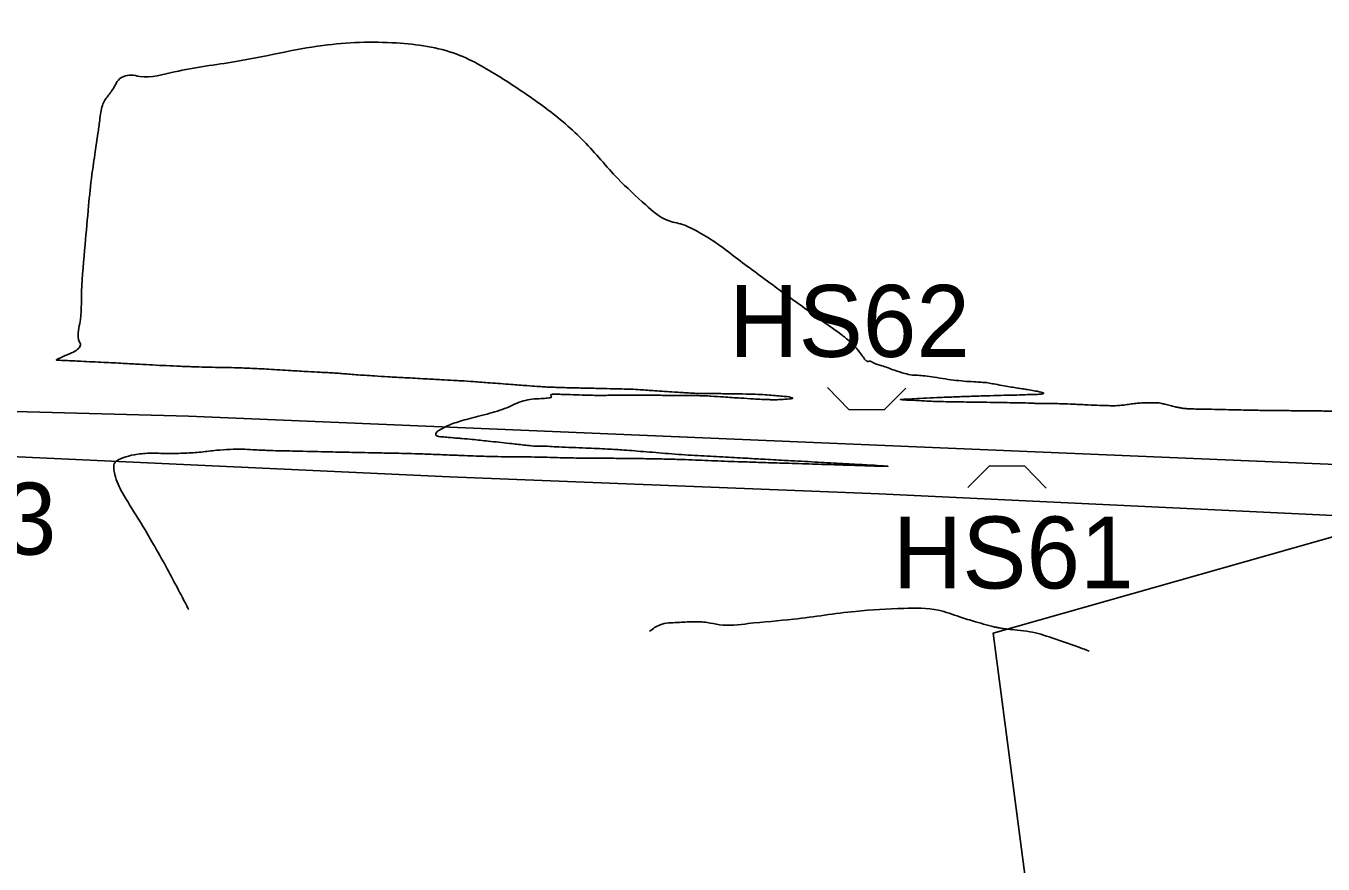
# Model space of a CAD drawing. Extents: x -478232 to -472707, y -1118753 to -1113967.
# Drawn here: x -477613.4 to -477433.2, y -1117465.6 to -1117349.2 of the extents above; entities that cross this region are included whole.
import ezdxf

# ---------------------------------------------------------------- set-up
doc = ezdxf.new("R2010")
doc.units = 0
for name, color, linetype in [('DESQ_pomoc', 7, 'Continuous'), ('hospodářské sjezdy', 7, 'Continuous'), ('ObPÚ', 7, 'Continuous'), ('silnice', 7, 'Continuous'), ('Vrstevnice_vedlejsi', 7, 'Continuous')]:
    doc.layers.add(name, color=color, linetype=linetype)

msp = doc.modelspace()

# ---------------------------------------------------------------- linework, layer by layer
at = {"layer": 'DESQ_pomoc'}
msp.add_lwpolyline([(-477421.557, -1117417.2), (-477479.012, -1117433.518), (-477472.878, -1117480.495), (-477481.667, -1117549.548), (-477467.907, -1117654.92), (-477462.841, -1117804.599), (-477459.217, -1117906.221), (-477463.956, -1117960.587), (-477418.233, -1118072.943), (-477384.22, -1118141.946), (-477344.067, -1118184.315), (-477265.129, -1118290.773), (-477142.501, -1118220.428)], dxfattribs=at)
at = {"layer": 'hospodářské sjezdy'}
for p, q in [((-477499.054, -1117402.428), (-477502.044, -1117399.386)), ((-477491.124, -1117399.487), (-477494.169, -1117402.473)), ((-477494.169, -1117402.473), (-477499.054, -1117402.428)), ((-477482.552, -1117413.268), (-477479.505, -1117410.283)), ((-477479.505, -1117410.283), (-477474.62, -1117410.33)), ((-477474.62, -1117410.33), (-477471.631, -1117413.373))]:
    msp.add_line(p, q, dxfattribs=at)
at = {"layer": 'ObPÚ'}
msp.add_lwpolyline([(-477428.82, -1117417.33), (-477494.83, -1117414.18), (-477554.51, -1117411.78), (-477621.5, -1117408.68), (-477644.72, -1117408.28), (-477682.13, -1117413.46), (-477685.93, -1117414.02), (-477688.8, -1117414.36), (-477691.73, -1117414.77), (-477738.55, -1117419.44), (-477782.49, -1117430.5), (-477808.98, -1117437.26), (-477845.5, -1117449.81), (-477945.12, -1117479.46), (-478009.37, -1117499.81)], dxfattribs=at)
at = {"layer": 'silnice'}
msp.add_lwpolyline([(-478068.596, -1117511.329), (-477917.95, -1117462.993), (-477779.219, -1117418.245), (-477732.944, -1117407.585), (-477720.808, -1117405.048), (-477704.588, -1117403.835), (-477689.402, -1117401.926), (-477652.852, -1117401.691), (-477590.784, -1117403.37), (-477332.447, -1117414.279), (-477204.956, -1117416.797), (-477142.049, -1117416.797), (-477096.756, -1117410.083), (-477036.34, -1117397.174), (-476978.492, -1117379.033), (-476883.712, -1117344.626), (-476756.221, -1117298.47), (-476633.763, -1117254.832), (-476588.47, -1117242.245), (-476550.726, -1117234.692), (-476503.755, -1117230.496), (-476424.073, -1117228.817), (-476282.324, -1117220.425)], dxfattribs=at)
at = {"layer": 'Vrstevnice_vedlejsi'}
for points in [[(-477242.816, -1117401.206), (-477242.33, -1117400.788), (-477241.801, -1117400.341), (-477241.229, -1117399.866), (-477240.615, -1117399.363), (-477236.987, -1117397.929), (-477230.346, -1117395.561), (-477220.692, -1117392.262), (-477213.029, -1117389.419), (-477207.358, -1117387.033), (-477203.679, -1117385.104), (-477198.765, -1117383.705), (-477192.616, -1117382.835), (-477185.231, -1117382.494), (-477180.359, -1117379.804), (-477178.001, -1117374.763), (-477178.155, -1117367.373), (-477179.951, -1117358.721), (-477183.387, -1117348.807), (-477188.465, -1117337.631), (-477192.245, -1117329.464), (-477194.727, -1117324.304), (-477195.91, -1117322.151), (-477197.022, -1117320.01), (-477198.062, -1117317.881), (-477199.031, -1117315.762), (-477201.828, -1117310.612), (-477206.453, -1117302.429), (-477212.906, -1117291.215), (-477218.991, -1117279.805), (-477224.706, -1117268.2), (-477230.053, -1117256.4), (-477233.791, -1117248.023), (-477235.922, -1117243.067), (-477236.445, -1117241.534), (-477237.131, -1117240.196), (-477237.979, -1117239.054), (-477238.989, -1117238.108), (-477240.099, -1117237.792), (-477241.308, -1117238.108), (-477242.616, -1117239.054), (-477247.496, -1117242.927), (-477255.949, -1117249.728), (-477267.975, -1117259.456), (-477276.908, -1117266.227), (-477282.75, -1117270.039), (-477285.501, -1117270.894), (-477290.862, -1117272.253), (-477298.834, -1117274.115), (-477309.417, -1117276.481), (-477320.28, -1117277.55), (-477331.422, -1117277.32), (-477342.843, -1117275.793), (-477351.095, -1117274.483), (-477356.177, -1117273.39), (-477358.088, -1117272.515), (-477363.807, -1117268.569), (-477373.333, -1117261.552), (-477386.667, -1117251.464), (-477395.708, -1117244.586), (-477400.459, -1117240.917), (-477400.917, -1117240.459), (-477405.515, -1117237.519), (-477414.252, -1117232.098), (-477427.127, -1117224.195), (-477436.796, -1117218.202), (-477443.259, -1117214.119), (-477446.516, -1117211.946), (-477449.727, -1117209.411), (-477452.893, -1117206.515), (-477456.014, -1117203.258), (-477459.048, -1117199.241), (-477461.994, -1117194.464), (-477464.853, -1117188.928), (-477466.734, -1117184.683), (-477467.638, -1117181.729), (-477467.564, -1117180.066), (-477467.628, -1117178.904), (-477467.829, -1117178.243), (-477468.169, -1117178.084), (-477468.447, -1117177.976), (-477468.662, -1117177.92), (-477468.815, -1117177.914), (-477468.774, -1117177.844), (-477468.538, -1117177.708), (-477468.108, -1117177.506), (-477467.675, -1117177.3), (-477467.24, -1117177.089), (-477466.803, -1117176.874), (-477466.105, -1117176.551), (-477465.147, -1117176.119), (-477463.929, -1117175.579), (-477461.972, -1117174.773), (-477459.277, -1117173.703), (-477455.843, -1117172.368), (-477453.286, -1117171.289), (-477451.604, -1117170.465)], [(-477560, -1117291.244), (-477566.955, -1117290.703), (-477572.559, -1117290.73), (-477580.289, -1117291.053), (-477590.144, -1117291.672), (-477599.448, -1117292.43), (-477608.201, -1117293.327), (-477616.402, -1117294.362), (-477623.179, -1117297.786), (-477628.532, -1117303.598), (-477632.462, -1117311.799), (-477635.234, -1117317.515), (-477636.85, -1117320.745), (-477637.308, -1117321.489), (-477637.862, -1117322.307), (-477638.511, -1117323.197), (-477639.255, -1117324.161), (-477640.286, -1117325.39), (-477641.603, -1117326.884), (-477643.205, -1117328.643), (-477644.962, -1117330.8), (-477646.874, -1117333.353), (-477648.94, -1117336.304), (-477650.379, -1117338.35), (-477651.193, -1117339.491), (-477651.38, -1117339.728), (-477651.613, -1117339.807), (-477651.892, -1117339.73), (-477652.217, -1117339.495), (-477652.693, -1117339.69), (-477653.319, -1117340.312), (-477654.095, -1117341.364), (-477655.093, -1117343.008), (-477656.315, -1117345.246), (-477657.76, -1117348.077), (-477658.682, -1117350.137), (-477659.083, -1117351.426), (-477658.962, -1117351.944), (-477659.599, -1117353.56), (-477660.994, -1117356.275), (-477663.148, -1117360.088), (-477664.694, -1117362.921), (-477665.633, -1117364.773), (-477665.966, -1117365.645), (-477666.773, -1117366.866), (-477668.055, -1117368.437), (-477669.813, -1117370.359), (-477671.229, -1117372.05), (-477672.304, -1117373.51), (-477673.037, -1117374.74), (-477673.862, -1117375.748), (-477674.779, -1117376.534), (-477675.788, -1117377.099), (-477676.742, -1117377.638), (-477677.641, -1117378.153), (-477678.485, -1117378.642), (-477679.333, -1117379.521), (-477680.185, -1117380.789), (-477681.041, -1117382.447), (-477681.49, -1117384.046), (-477681.533, -1117385.585), (-477681.168, -1117387.067), (-477681.316, -1117388.188), (-477681.976, -1117388.95), (-477683.149, -1117389.352), (-477683.785, -1117390.175), (-477683.885, -1117391.417), (-477683.449, -1117393.079), (-477683.513, -1117394.312), (-477684.078, -1117395.114), (-477685.144, -1117395.487), (-477685.939, -1117395.751), (-477686.463, -1117395.907), (-477686.718, -1117395.954), (-477686.939, -1117395.99), (-477687.126, -1117396.014), (-477687.279, -1117396.025), (-477687.704, -1117396.038), (-477688.399, -1117396.053), (-477689.366, -1117396.069), (-477690.19, -1117395.962), (-477690.871, -1117395.732), (-477691.409, -1117395.38), (-477691.907, -1117395.109), (-477692.367, -1117394.92), (-477692.788, -1117394.813), (-477693.123, -1117394.709), (-477693.373, -1117394.61), (-477693.537, -1117394.515), (-477693.67, -1117394.45), (-477693.774, -1117394.413), (-477693.847, -1117394.406), (-477693.928, -1117394.43), (-477694.017, -1117394.485), (-477694.114, -1117394.571), (-477694.592, -1117394.718), (-477695.45, -1117394.927)], [(-477495.127, -1117335.127), (-477511.712, -1117338.553), (-477521.011, -1117337.443), (-477531.316, -1117333.51), (-477542.627, -1117326.753), (-477550.841, -1117321.897), (-477555.959, -1117318.94), (-477557.979, -1117317.884), (-477563.123, -1117316.885), (-477571.391, -1117315.942), (-477582.781, -1117315.057), (-477591.023, -1117314.508), (-477596.115, -1117314.294), (-477598.057, -1117314.416), (-477599.891, -1117314.566), (-477601.616, -1117314.742), (-477603.233, -1117314.947), (-477604.569, -1117315.621), (-477605.624, -1117316.767), (-477606.399, -1117318.384), (-477608.304, -1117321.719), (-477611.342, -1117326.774), (-477615.51, -1117333.547), (-477619.979, -1117340.25), (-477624.748, -1117346.881), (-477629.817, -1117353.44), (-477633.361, -1117359.059), (-477635.379, -1117363.738), (-477635.872, -1117367.476), (-477636.56, -1117371.199), (-477637.443, -1117374.909), (-477638.521, -1117378.604), (-477639.377, -1117382.031), (-477640.009, -1117385.19), (-477640.419, -1117388.082), (-477640.785, -1117390.136), (-477641.106, -1117391.354), (-477641.382, -1117391.735), (-477641.698, -1117392.233), (-477642.053, -1117392.847), (-477642.449, -1117393.578), (-477642.545, -1117394.166), (-477642.342, -1117394.61), (-477641.839, -1117394.91), (-477641.625, -1117395.129), (-477641.7, -1117395.269), (-477642.063, -1117395.328), (-477642.557, -1117395.371), (-477643.181, -1117395.398), (-477643.936, -1117395.409), (-477644.487, -1117395.416), (-477644.834, -1117395.419), (-477644.977, -1117395.418), (-477645.44, -1117395.437), (-477646.223, -1117395.478), (-477647.327, -1117395.539), (-477648.287, -1117395.586), (-477649.105, -1117395.618), (-477649.781, -1117395.636), (-477650.529, -1117395.622), (-477651.351, -1117395.575), (-477652.246, -1117395.495), (-477653.089, -1117395.458), (-477653.88, -1117395.466), (-477654.618, -1117395.517), (-477655.514, -1117395.581), (-477656.567, -1117395.657), (-477657.777, -1117395.746), (-477658.796, -1117395.828), (-477659.624, -1117395.904), (-477660.261, -1117395.973), (-477661.317, -1117396.007), (-477662.793, -1117396.004), (-477664.688, -1117395.966), (-477665.997, -1117395.925), (-477666.721, -1117395.883), (-477666.859, -1117395.838), (-477667.114, -1117395.731), (-477667.487, -1117395.563), (-477667.978, -1117395.332), (-477668.383, -1117395.039), (-477668.702, -1117394.683), (-477668.934, -1117394.264), (-477669.163, -1117393.971), (-477669.387, -1117393.804), (-477669.607, -1117393.763), (-477669.885, -1117393.684), (-477670.219, -1117393.568), (-477670.611, -1117393.414), (-477670.803, -1117393.149), (-477670.795, -1117392.772), (-477670.589, -1117392.285), (-477670.483, -1117391.911), (-477670.48, -1117391.65), (-477670.578, -1117391.502), (-477670.739, -1117391.523), (-477670.964, -1117391.713)], [(-477547.057, -1117356.544), (-477553.529, -1117353.088), (-477561.882, -1117351.53), (-477572.116, -1117351.871), (-477584.232, -1117354.11), (-477592.716, -1117355.544), (-477597.566, -1117356.173), (-477598.783, -1117355.997), (-477599.771, -1117356.168), (-477600.531, -1117356.684), (-477601.061, -1117357.546), (-477601.551, -1117358.298), (-477602.002, -1117358.939), (-477602.412, -1117359.469), (-477602.735, -1117360.205), (-477602.973, -1117361.146), (-477603.124, -1117362.291), (-477603.379, -1117364.123), (-477603.738, -1117366.64), (-477604.201, -1117369.843), (-477604.671, -1117374.143), (-477605.147, -1117379.539), (-477605.629, -1117386.031), (-477605.897, -1117390.519), (-477605.953, -1117393.003), (-477605.795, -1117393.483), (-477606.068, -1117393.971), (-477606.774, -1117394.465), (-477607.91, -1117394.966), (-477608.683, -1117395.313), (-477609.09, -1117395.506), (-477609.132, -1117395.543), (-477609.139, -1117395.569), (-477609.111, -1117395.582), (-477609.047, -1117395.583), (-477608.993, -1117395.585), (-477608.95, -1117395.587), (-477608.917, -1117395.589), (-477607.842, -1117395.642), (-477605.725, -1117395.746), (-477602.565, -1117395.902), (-477599.853, -1117396.04), (-477597.587, -1117396.161), (-477595.769, -1117396.264), (-477593.874, -1117396.358), (-477591.902, -1117396.442), (-477589.854, -1117396.517), (-477587.923, -1117396.575), (-477586.108, -1117396.616), (-477584.411, -1117396.64), (-477582.257, -1117396.72), (-477579.647, -1117396.854), (-477576.581, -1117397.043), (-477574.191, -1117397.186), (-477572.476, -1117397.281), (-477571.436, -1117397.33), (-477570.44, -1117397.388), (-477569.488, -1117397.455), (-477568.579, -1117397.532), (-477567.518, -1117397.613), (-477566.304, -1117397.699), (-477564.938, -1117397.79), (-477563.079, -1117397.901), (-477560.727, -1117398.033), (-477557.883, -1117398.185), (-477555.632, -1117398.307), (-477553.973, -1117398.399), (-477552.907, -1117398.461), (-477551.216, -1117398.577), (-477548.9, -1117398.747), (-477545.961, -1117398.971), (-477543.777, -1117399.136), (-477542.351, -1117399.241), (-477541.681, -1117399.287), (-477540.95, -1117399.327), (-477540.156, -1117399.361), (-477539.3, -1117399.389), (-477537.852, -1117399.427), (-477535.812, -1117399.475), (-477533.18, -1117399.533), (-477531.228, -1117399.578), (-477529.955, -1117399.611), (-477529.361, -1117399.631), (-477528.052, -1117399.706), (-477526.027, -1117399.837), (-477523.287, -1117400.022), (-477521.342, -1117400.147), (-477520.193, -1117400.212), (-477519.839, -1117400.216), (-477518.821, -1117400.228), (-477517.138, -1117400.246), (-477514.791, -1117400.271), (-477512.839, -1117400.311), (-477511.284, -1117400.368), (-477510.126, -1117400.44), (-477509.042, -1117400.531), (-477508.034, -1117400.639)], [(-477465.81, -1117401.807), (-477467.853, -1117401.711), (-477469.483, -1117401.65), (-477470.699, -1117401.625), (-477471.502, -1117401.636), (-477472.266, -1117401.631), (-477472.992, -1117401.61), (-477473.68, -1117401.572), (-477475.37, -1117401.529), (-477478.062, -1117401.478), (-477481.757, -1117401.421), (-477484.381, -1117401.381), (-477485.933, -1117401.359), (-477486.415, -1117401.354), (-477487.287, -1117401.321), (-477488.55, -1117401.26), (-477490.204, -1117401.17), (-477491.309, -1117401.11), (-477491.868, -1117401.081), (-477491.878, -1117401.081), (-477491.885, -1117401.08), (-477491.891, -1117401.076), (-477491.893, -1117401.071), (-477491.894, -1117401.067), (-477491.892, -1117401.063), (-477491.887, -1117401.06), (-477491.875, -1117401.058), (-477491.855, -1117401.056), (-477491.827, -1117401.055), (-477491.219, -1117401.024), (-477490.031, -1117400.961), (-477488.263, -1117400.869), (-477486.338, -1117400.78), (-477484.255, -1117400.695), (-477482.016, -1117400.615), (-477479.912, -1117400.547), (-477477.943, -1117400.491), (-477476.109, -1117400.448), (-477474.559, -1117400.402), (-477473.292, -1117400.353), (-477472.309, -1117400.302), (-477471.989, -1117400.201), (-477472.332, -1117400.051), (-477473.338, -1117399.852), (-477474.227, -1117399.687), (-477474.997, -1117399.558), (-477475.649, -1117399.463), (-477476.484, -1117399.329), (-477477.503, -1117399.154), (-477478.704, -1117398.939), (-477479.519, -1117398.793), (-477479.949, -1117398.717), (-477479.994, -1117398.711), (-477480.47, -1117398.679), (-477481.379, -1117398.621), (-477482.718, -1117398.537), (-477484.139, -1117398.4), (-477485.64, -1117398.209), (-477487.222, -1117397.965), (-477488.516, -1117397.792), (-477489.521, -1117397.691), (-477490.237, -1117397.662), (-477491.302, -1117397.432), (-477492.716, -1117397.001), (-477494.479, -1117396.369), (-477495.659, -1117395.95), (-477496.257, -1117395.744), (-477496.271, -1117395.751), (-477496.308, -1117395.757), (-477496.367, -1117395.762), (-477496.447, -1117395.765), (-477496.505, -1117395.761), (-477496.539, -1117395.753), (-477496.551, -1117395.738), (-477496.586, -1117395.707), (-477496.645, -1117395.66), (-477496.728, -1117395.598), (-477496.981, -1117395.287), (-477497.405, -1117394.728), (-477497.999, -1117393.92), (-477498.917, -1117393.009), (-477500.16, -1117391.995), (-477501.727, -1117390.879), (-477503.712, -1117389.452), (-477506.116, -1117387.713), (-477508.939, -1117385.664), (-477511.742, -1117383.602), (-477514.524, -1117381.527), (-477517.287, -1117379.44), (-477519.836, -1117377.849), (-477522.172, -1117376.754), (-477524.294, -1117376.156), (-477527.284, -1117374.028), (-477531.14, -1117370.371), (-477535.863, -1117365.186), (-477541.169, -1117360.577), (-477547.057, -1117356.544)], [(-477414.713, -1117402.635), (-477414.793, -1117402.52), (-477414.862, -1117402.382), (-477414.919, -1117402.22), (-477414.964, -1117402.035), (-477414.971, -1117401.827), (-477414.94, -1117401.597), (-477414.871, -1117401.344), (-477414.776, -1117401.092), (-477414.656, -1117400.84), (-477414.509, -1117400.588), (-477414.5, -1117400.343), (-477414.626, -1117400.104), (-477414.889, -1117399.873), (-477415.271, -1117399.599), (-477415.77, -1117399.284), (-477416.387, -1117398.926), (-477417.221, -1117398.692), (-477418.272, -1117398.582), (-477419.539, -1117398.595), (-477420.369, -1117398.755), (-477420.761, -1117399.064), (-477420.717, -1117399.521), (-477420.751, -1117399.907), (-477420.865, -1117400.222), (-477421.058, -1117400.465), (-477421.095, -1117400.623), (-477420.976, -1117400.696), (-477420.702, -1117400.684), (-477420.48, -1117400.735), (-477420.311, -1117400.849), (-477420.194, -1117401.026), (-477420.072, -1117401.2), (-477419.944, -1117401.372), (-477419.811, -1117401.542), (-477419.721, -1117401.681), (-477419.672, -1117401.789), (-477419.665, -1117401.866), (-477419.669, -1117401.942), (-477419.684, -1117402.017), (-477419.709, -1117402.092), (-477419.743, -1117402.15), (-477419.788, -1117402.192), (-477419.844, -1117402.219), (-477419.949, -1117402.313), (-477420.105, -1117402.475), (-477420.31, -1117402.706), (-477420.47, -1117402.874), (-477420.583, -1117402.98), (-477420.65, -1117403.024), (-477420.838, -1117403.102), (-477421.149, -1117403.215), (-477421.582, -1117403.362), (-477421.986, -1117403.481), (-477422.363, -1117403.572), (-477422.711, -1117403.635), (-477423.284, -1117403.642), (-477424.082, -1117403.593), (-477425.105, -1117403.49), (-477426.142, -1117403.353), (-477427.192, -1117403.183), (-477428.258, -1117402.98), (-477429.215, -1117402.833), (-477430.065, -1117402.74), (-477430.807, -1117402.703), (-477432.264, -1117402.67), (-477434.436, -1117402.641), (-477437.323, -1117402.616), (-477439.628, -1117402.593), (-477441.351, -1117402.574), (-477442.491, -1117402.558), (-477443.834, -1117402.533), (-477445.382, -1117402.5), (-477447.133, -1117402.459), (-477448.678, -1117402.425), (-477450.018, -1117402.398), (-477451.151, -1117402.378), (-477452.057, -1117402.337), (-477452.737, -1117402.276), (-477453.19, -1117402.193), (-477453.748, -1117402.072), (-477454.411, -1117401.913), (-477455.18, -1117401.716), (-477455.749, -1117401.582), (-477456.119, -1117401.512), (-477456.289, -1117401.504), (-477456.686, -1117401.505), (-477457.31, -1117401.514), (-477458.161, -1117401.531), (-477458.996, -1117401.585), (-477459.816, -1117401.675), (-477460.62, -1117401.803), (-477461.416, -1117401.885), (-477462.205, -1117401.921), (-477462.986, -1117401.912), (-477464.188, -1117401.874), (-477465.81, -1117401.807)], [(-477508.034, -1117400.639), (-477507.101, -1117400.766), (-477506.856, -1117400.876), (-477507.298, -1117400.971), (-477508.427, -1117401.05), (-477509.246, -1117401.096), (-477509.755, -1117401.108), (-477509.953, -1117401.088), (-477510.253, -1117401.069), (-477510.655, -1117401.052), (-477511.159, -1117401.037), (-477512.298, -1117400.974), (-477514.07, -1117400.864), (-477516.476, -1117400.707), (-477518.174, -1117400.599), (-477519.164, -1117400.542), (-477519.447, -1117400.536), (-477519.779, -1117400.528), (-477520.161, -1117400.519), (-477520.592, -1117400.509), (-477521.577, -1117400.499), (-477523.115, -1117400.489), (-477525.207, -1117400.48), (-477527.074, -1117400.473), (-477528.718, -1117400.468), (-477530.139, -1117400.466), (-477531.407, -1117400.469), (-477532.522, -1117400.477), (-477533.484, -1117400.49), (-477534.682, -1117400.479), (-477536.115, -1117400.442), (-477537.784, -1117400.381), (-477539.025, -1117400.343), (-477539.837, -1117400.327), (-477540.221, -1117400.333), (-477540.438, -1117400.397), (-477540.488, -1117400.519), (-477540.371, -1117400.698), (-477540.711, -1117400.834), (-477541.506, -1117400.928), (-477542.757, -1117400.98), (-477543.965, -1117401.187), (-477545.131, -1117401.551), (-477546.254, -1117402.07), (-477547.521, -1117402.546), (-477548.932, -1117402.978), (-477550.486, -1117403.365), (-477551.859, -1117403.732), (-477553.051, -1117404.079), (-477554.061, -1117404.405), (-477554.943, -1117404.773), (-477555.699, -1117405.182), (-477556.327, -1117405.633), (-477556.441, -1117405.967), (-477556.038, -1117406.182), (-477555.121, -1117406.28), (-477554.279, -1117406.361), (-477553.512, -1117406.424), (-477552.821, -1117406.471), (-477551.368, -1117406.609), (-477549.155, -1117406.841), (-477546.181, -1117407.166), (-477544.191, -1117407.383), (-477543.183, -1117407.492), (-477543.158, -1117407.494), (-477543.14, -1117407.495), (-477543.128, -1117407.496), (-477543.122, -1117407.497), (-477541.864, -1117407.548), (-477539.353, -1117407.649), (-477535.589, -1117407.801), (-477532.576, -1117407.943), (-477530.313, -1117408.076), (-477528.801, -1117408.198), (-477527.185, -1117408.328), (-477525.465, -1117408.466), (-477523.641, -1117408.613), (-477521.836, -1117408.741), (-477520.05, -1117408.85), (-477518.283, -1117408.942), (-477516.581, -1117409.033), (-477514.945, -1117409.124), (-477513.375, -1117409.215), (-477511.065, -1117409.345), (-477508.016, -1117409.513), (-477504.227, -1117409.721), (-477500.731, -1117409.914), (-477497.526, -1117410.093), (-477494.613, -1117410.257), (-477493.633, -1117410.335), (-477494.588, -1117410.328), (-477497.476, -1117410.236), (-477500.652, -1117410.136), (-477504.115, -1117410.028), (-477507.866, -1117409.912), (-477510.998, -1117409.814), (-477513.511, -1117409.732)], [(-477513.511, -1117409.732), (-477515.405, -1117409.668), (-477517.254, -1117409.599), (-477519.058, -1117409.525), (-477520.817, -1117409.447), (-477522.721, -1117409.381), (-477524.771, -1117409.328), (-477526.965, -1117409.288), (-477529.386, -1117409.255), (-477532.034, -1117409.23), (-477534.907, -1117409.213), (-477537.286, -1117409.186), (-477539.169, -1117409.149), (-477540.557, -1117409.101), (-477542.227, -1117409.063), (-477544.177, -1117409.034), (-477546.409, -1117409.015), (-477548.263, -1117408.988), (-477549.741, -1117408.955), (-477550.842, -1117408.915), (-477552.44, -1117408.854), (-477554.534, -1117408.773), (-477557.124, -1117408.67), (-477559.347, -1117408.593), (-477561.202, -1117408.541), (-477562.691, -1117408.514), (-477563.953, -1117408.49), (-477564.987, -1117408.47), (-477565.795, -1117408.455), (-477567.715, -1117408.413), (-477570.747, -1117408.346), (-477574.891, -1117408.254), (-477577.805, -1117408.187), (-477579.487, -1117408.145), (-477579.938, -1117408.128), (-477580.73, -1117408.091), (-477581.863, -1117408.034), (-477583.338, -1117407.957), (-477585.02, -1117407.986), (-477586.911, -1117408.12), (-477589.011, -1117408.359), (-477591.264, -1117408.507), (-477593.672, -1117408.563), (-477596.234, -1117408.529), (-477598.311, -1117408.731), (-477599.903, -1117409.169), (-477601.01, -1117409.843), (-477601.03, -1117411.462), (-477599.962, -1117414.025), (-477597.806, -1117417.534), (-477595.866, -1117420.813), (-477594.141, -1117423.862), (-477592.631, -1117426.681), (-477591.02, -1117429.727), (-477590.744, -1117430.252)], [(-477526.753, -1117433.267), (-477525.277, -1117432.359), (-477522.871, -1117432.043), (-477520.695, -1117431.936), (-477518.75, -1117432.038), (-477517.035, -1117432.347), (-477513.028, -1117432.193), (-477506.73, -1117431.575), (-477498.14, -1117430.492), (-477491.433, -1117430.078), (-477486.61, -1117430.332), (-477483.669, -1117431.254), (-477481.458, -1117431.933), (-477479.979, -1117432.368), (-477479.23, -1117432.559), (-477478.616, -1117432.704), (-477478.138, -1117432.801), (-477477.795, -1117432.852), (-477476.977, -1117432.955), (-477475.683, -1117433.11), (-477473.914, -1117433.317), (-477470.873, -1117434.175), (-477466.559, -1117435.683), (-477465.699, -1117436.005)]]:
    msp.add_spline(points, degree=3, dxfattribs=at)

# ---------------------------------------------------------------- texts
at = {"layer": 'hospodářské sjezdy'}
for s, p in [('HS62', (-477515.695, -1117395.143)), ('HS63', (-477642.594, -1117422.613)), ('HS61', (-477492.963, -1117427.316))]:
    msp.add_text(s, height=10, rotation=359.99999, dxfattribs=at).set_placement(p)

doc.saveas('drawing.dxf')
